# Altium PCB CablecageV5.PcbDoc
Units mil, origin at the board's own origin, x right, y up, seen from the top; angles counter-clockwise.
Board outline 745.03 x 1580.03 mil, 2 copper layers (Top Layer, Bottom Layer); 12 components, 19 nets, 69 pads, 70 vias.
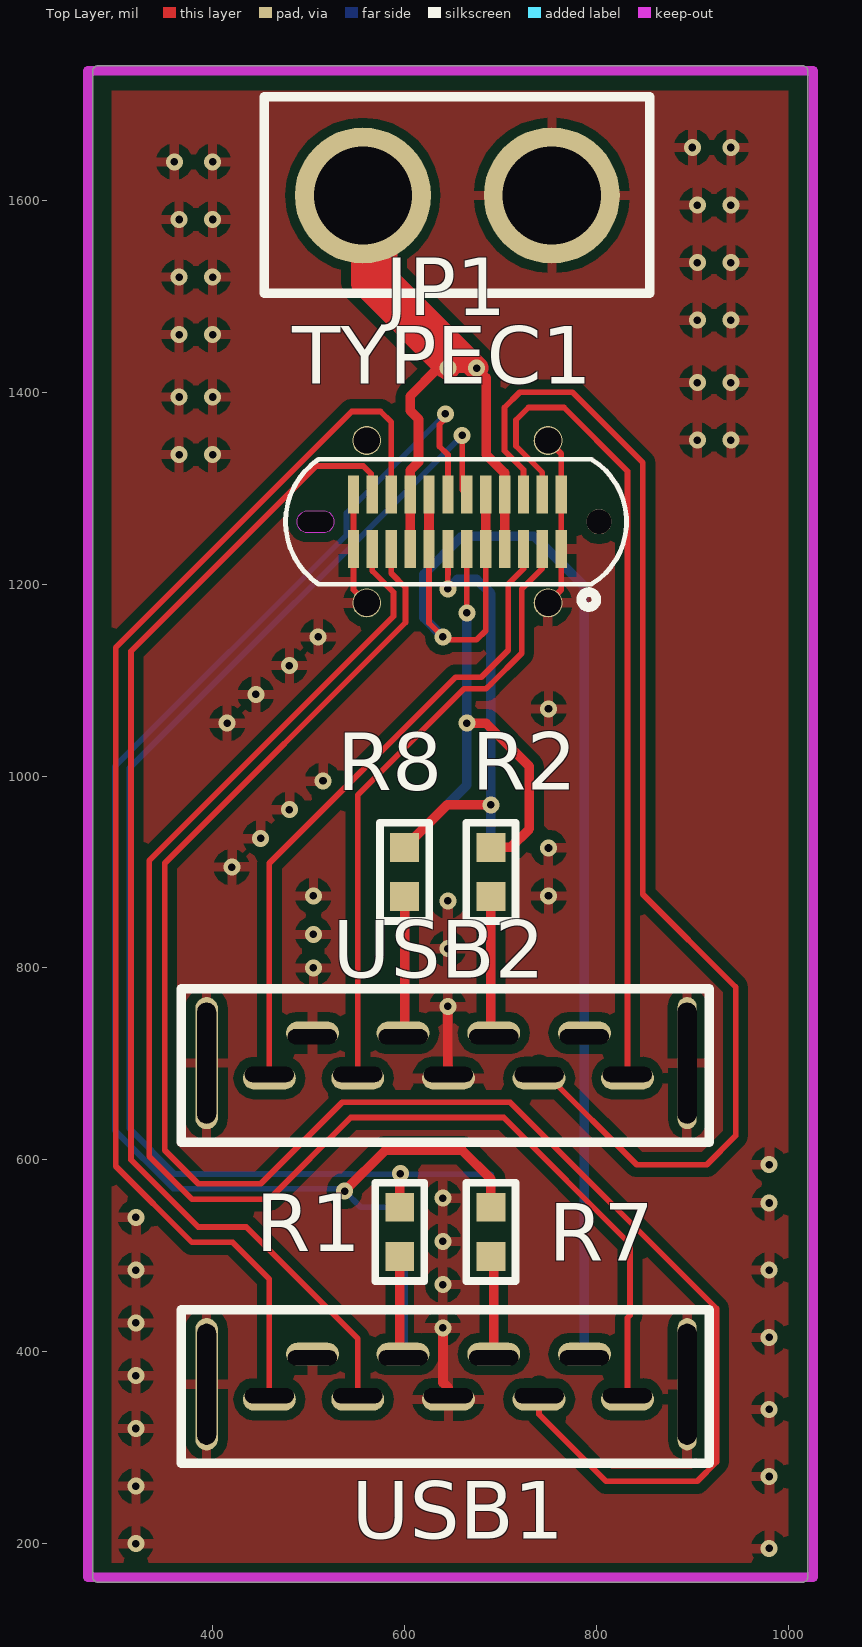
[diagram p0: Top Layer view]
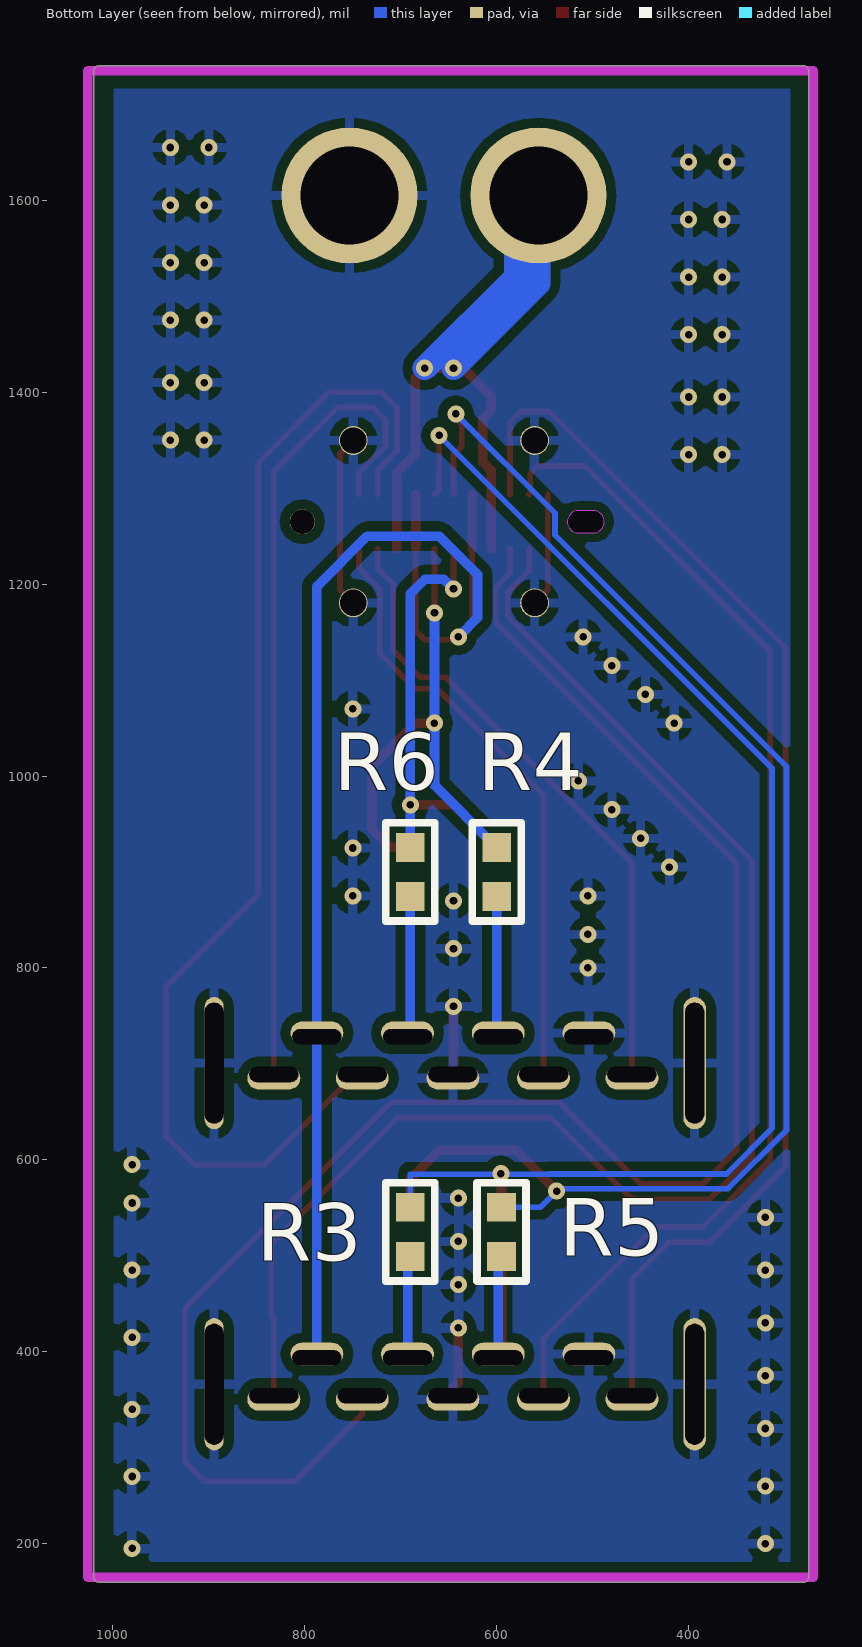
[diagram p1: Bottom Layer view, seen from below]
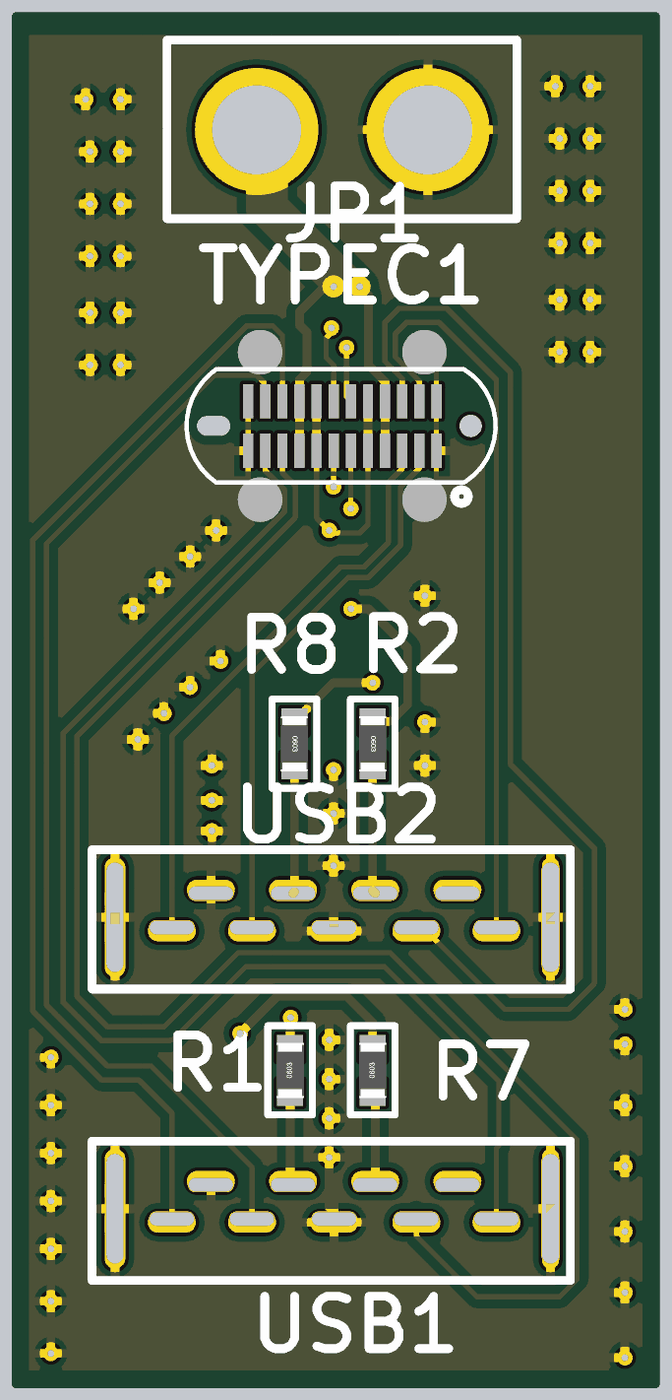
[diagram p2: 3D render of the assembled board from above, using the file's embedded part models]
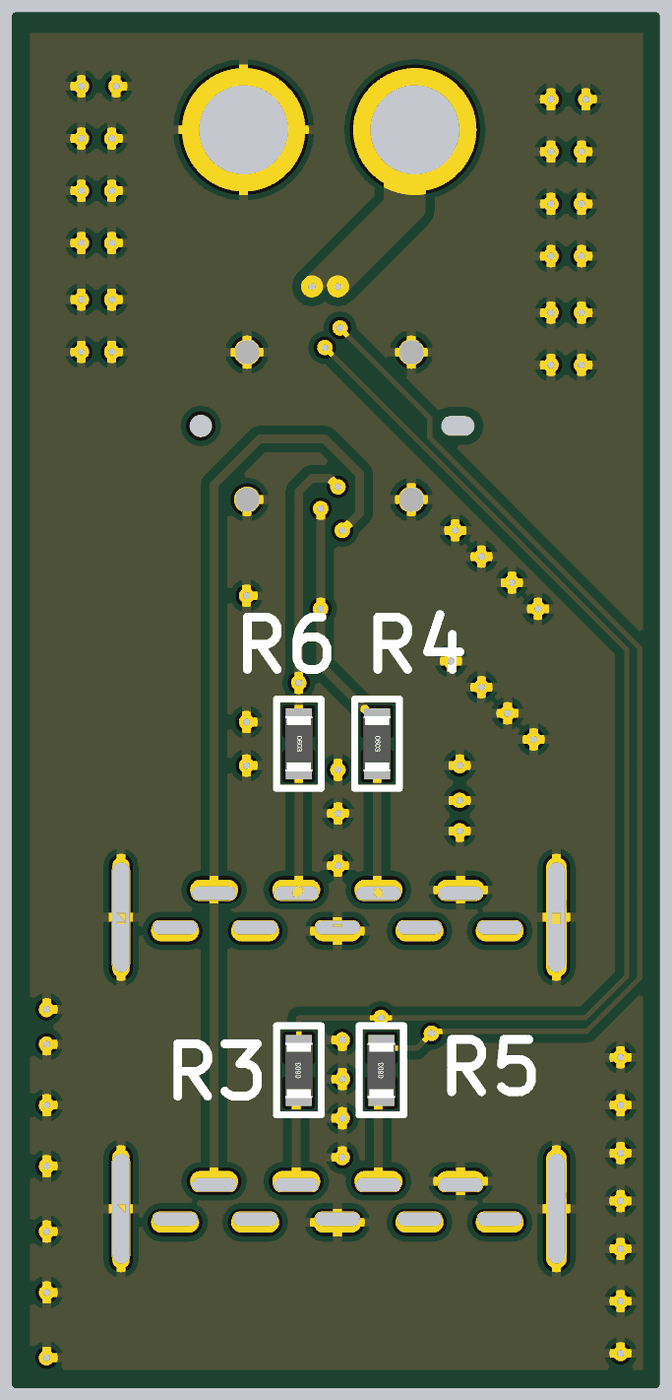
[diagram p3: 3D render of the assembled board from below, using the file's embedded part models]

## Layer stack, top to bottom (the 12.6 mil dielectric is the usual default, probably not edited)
Top Solder: solder mask 0.4, Solder Resist, Dk 3.5
Top Layer: signal copper 1.4
Dielectric 1: dielectric 12.6, FR-4, Dk 4.8
Bottom Layer: signal copper 1.4
Bottom Solder: solder mask 0.4, Solder Resist, Dk 3.5

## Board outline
274.99,165 274.99,1735 cw(c280,1735) 280,1740.02 1015,1740.02 cw(c1015,1735) 1020.01,1735 1020.01,165 cw(c1015,165) 1015,159.99 280,159.99 cw(c280,165)

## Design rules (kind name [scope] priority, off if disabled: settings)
Clearance [All] p1: gap=10 ignorepadtopadclearanceinfootprint=TRUE except(0: Arc-Hole Track-Hole SMDPad-Hole THPad-Hole Via-Hole Fill-Hole Poly-Hole Region-Hole Text-Hole; 6: Arc-Arc Arc-Track Arc-SMDPad Arc-THPad Arc-Via Track-Track Track-SMDPad Track-THPad Track-Via SMDPad-SMDPad SMDPad-THPad SMDPad-Via THPad-THPad THPad-Via Via-Via)
DiffPairsRouting [All] p1: maxlimit=50 minlimit=6 mostfreqgap=6 toplayer_minwidth=6 toplayer_maxwidth=15 toplayer_prefwidth=15 bottomlayer_minwidth=6 bottomlayer_maxwidth=15 bottomlayer_prefwidth=15 maxuncoupledlength=500
PolygonConnect [All] p1: connectstyle=Relief reliefconductorwidth=10 reliefentries=4 polygonreliefangle="90 Angle" airgapwidth=10
RoutingVias [All] p1: holewidth=28 width=50 viastyle="Through Hole" minholewidth=28 minwidth=50 maxholewidth=28 maxwidth=50
SolderMaskExpansion [All] p1: expansion=4
Width [All] p1: maxlimit=100 minlimit=6 preferedwidth=20 minimp=50.000000 maximp=50.000000 favimp=50.000000
29 further rules are at their usual default settings.

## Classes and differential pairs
component class draft_v2: JP1 R1 R2 R3 R4 R5 R6 R7 R8 TYPEC1 USB2
differential pair USB3-T: +USB3-T_P -USB3-T_N
differential pair USB3-T2: +USB3-T2_P -USB3-T2_N
differential pair USB3-R: +USB3-R_P -USB3-R_N
differential pair USB3-R2: +USB3-R2_P -USB3-R2_N
differential pair D4: +D4_P -D4_N
differential pair D3: +D3_P -D3_N

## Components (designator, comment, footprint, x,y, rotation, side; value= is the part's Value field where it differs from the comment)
JP1 "HDR-1X2" XT30 655,1605 r0 top
R1 "1K" "R 0603_L" 595,525 r90 top
R2 "1K" "R 0603_L" 690,900 r270 top
R3 "1K" "R 0603_L" 690,525 r90 bottom
R4 "1K" "R 0603_L" 600,900 r270 bottom
R5 "1K" "R 0603_L" 595,525 r90 bottom
R6 "1K" "R 0603_L" 690,900 r270 bottom
R7 "1K" "R 0603_L" 690,525 r90 top
R8 "1K" "R 0603_L" 600,900 r270 top
TYPEC1 "USB31-TYPEC-33141-2FS" USB-C-SMD_TYPEC-501S-ACP24H104 655,1265 r180 top
USB1 "FUS301-FDBU1K" USB3.0-MALE-0.8D 787.4,393.7 r180 top
USB2 "FUS301-FDBU1K" USB3.0-MALE-0.8D 787.4,728.35 r180 top

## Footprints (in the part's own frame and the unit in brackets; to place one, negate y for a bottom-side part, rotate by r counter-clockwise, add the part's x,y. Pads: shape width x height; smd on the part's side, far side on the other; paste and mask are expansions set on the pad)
"R 0603_L" [mil] "1/10W贴片电阻                 淘宝ID:黄晶宝石"
  rect 30x30 smd: 1(-25.59,0) 2(25.59,0)
  silkscreen extent -51,-26 51,26, body extent -31,-16 31,16, height 16
USB3.0-MALE-0.8D [mm]
  oval 1.4x0.6 hole 0.4 slot 1.3 at 0 deg copper offset 0,-0.1: 1(0,0) 2(2.4,0) 3(4.8,0) 4(7.2,0)
  oval 1.4x0.6 hole 0.4 slot 1.3 at 0 deg copper offset 0,0.1: 5(8.34,1) 6(6,1) 7(3.6,1) 8(1.2,1) 9(-1.14,1)
  oval 0.5x3.5 hole 3.2 slot 0.5 at 0 deg: 10(-2.72,0.7)
  oval 0.6x3.5 hole 3.2 slot 0.5 at 0 deg: 10(10,0.7)
  silkscreen extent -3.3,-1.27 10.67,2.79
USB-C-SMD_TYPEC-501S-ACP24H104 [mm]
  round 0.762 hole 0.7: 0(-2.4,2.15) 0(-2.4,-2.15) 0(2.4,2.15) 0(2.4,-2.15)
  rect 0.3x1 smd: A1(-2.75,0.72) A2(-2.25,0.72) A3(-1.75,0.72) A4(-1.25,0.72) A5(-0.75,0.72) A6(-0.25,0.72) A7(0.25,0.72) A8(0.75,0.72) A9(1.25,0.72) A10(1.75,0.72) A11(2.25,0.72) A12(2.75,0.72) B1(2.75,-0.72) B2(2.25,-0.72) B3(1.75,-0.72) B4(1.25,-0.72) B5(0.75,-0.72) B6(0.25,-0.72) B7(-0.25,-0.72) B8(-0.75,-0.72) B9(-1.25,-0.72) B10(-1.75,-0.72) B11(-2.25,-0.72) B12(-2.75,-0.72)
  round 0.66 hole 0.66 unplated: ""(-3.75,0)
  Keep-Out Layer board cut-out: 4.244,0 4.244,-0.056 4.203,-0.16 4.126,-0.241 4.024,-0.287 3.968,-0.29 3.968,-0.29 3.968,-0.29 3.556,-0.29 3.499,-0.289 3.393,-0.245 3.312,-0.163 3.268,-0.057 3.268,0 3.268,0 3.268,0 3.268,0.058 3.312,0.164 3.393,0.245 3.499,0.29 3.556,0.29 3.556,0.29 3.556,0.29 3.97,0.29 4.026,0.287 4.127,0.24 4.203,0.159 4.244,0.056 4.244,0 4.244,0 4.244,0 4.244,0
  Keep-Out Layer board cut-out: 3.97,-0.29 3.968,-0.29 3.968,-0.29 3.968,-0.29 3.968,-0.29 3.968,-0.29 3.968,-0.29 3.968,-0.29 3.968,-0.29
  silkscreen extent -4.48,-1.65 4.55,2.26
XT30 [mm]
  round 3.6 hole 2.6: 1(-2.5,0) 2(2.5,0)
  silkscreen extent -5.12,-2.59 5.09,2.62

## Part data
JP1: library part "Header 2", "2P接插件"
R1 R2 R3 R4 R5 R6 R7 R8: library part R, "贴片电阻"
TYPEC1: BOM_JLCPCB Part Class="Extended Part", BOM_Manufacturer="XKB Enterprise"
USB1 USB2: BOM_JLCPCB Part Class="Extended Part", BOM_Manufacturer=TXGA

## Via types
v1: diameter 17.72, hole 7.87, Top Layer to Bottom Layer, 70 vias

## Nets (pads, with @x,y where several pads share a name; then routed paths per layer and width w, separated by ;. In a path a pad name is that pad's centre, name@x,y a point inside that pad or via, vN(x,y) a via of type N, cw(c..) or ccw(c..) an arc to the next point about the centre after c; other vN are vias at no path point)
5.0V: TYPEC1.A5 TYPEC1.A8 TYPEC1.B5 TYPEC1.B8 USB1.1 USB2.1 | length 1428.8
  Top Layer w6: TYPEC1.A8 625.47,1159.53 v1(640,1145) 643,1142 675.03,1142 684.53,1151.5 TYPEC1.A5
  Top Layer w10: TYPEC1.A8 TYPEC1.B5 ; TYPEC1.A5 TYPEC1.B8
  Bottom Layer w10: v1(640,1145) 620,1165 620,1210 660,1250 735,1250 787.4,1197.6 USB2.1 USB1.1
D3_N: R4.2 R8.2 USB2.3 | length 293.4
  Top Layer w10: USB2.3 600,729.92 R8.2
  Bottom Layer w10: USB2.3 600,729.92 R4.2
D3_P: R2.2 R6.2 USB2.2 | length 294.5
  Top Layer w10: R2.2 690,731.26 USB2.2
  Bottom Layer w10: R6.2 690,731.26 USB2.2
D4_N: R1.1 R5.1 USB1.3 | length 214.2
  Top Layer w10: R1.1 595,397.12 USB1.3
  Bottom Layer w10: R5.1 598.43,495.98 USB1.3
D4_P: R3.1 R7.1 USB1.2 | length 213.8
  Top Layer w10: R7.1 692.91,496.5 USB1.2
  Bottom Layer w10: R3.1 692.91,496.49 USB1.2
GND: JP1.2 TYPEC1.0 TYPEC1.A1 TYPEC1.A12 TYPEC1.B1 TYPEC1.B12 USB1.4 USB1.7 USB1.10 USB2.4 USB2.7 USB2.10 | length 428
  Top Layer w6: TYPEC1.B1 TYPEC1.A12 546.73,1194.13 TYPEC1.0@560.51,1180.36 ; TYPEC1.0@749.49,1180.36 763.27,1194.13 TYPEC1.A1 TYPEC1.B12 763.27,1335.87 TYPEC1.0@749.49,1349.64
  Top Layer w10: v1(640,425) 640,367.87 645.67,362.2 ; v1(645,760) 645,697.52 645.67,696.85
  other v1: 980,195 320,200 320,260 980,270 320,320 980,340 320,375 980,415 320,430 640,470 320,485 980,485 640,515 320,540 980,555 640,560 980,595 505,800 645,820 505,835 645,870 505,875 750,875 420,905 750,925 450,935 480,965 515,995 415,1055 750,1070 445,1085 480,1115 510,1145 365,1335 400,1335 905,1350 940,1350 365,1395 400,1395 905,1410 940,1410 365,1460 400,1460 905,1475 940,1475 365,1520 400,1520 905,1535 940,1535 365,1580 400,1580 905,1595 940,1595 360,1640 400,1640 900,1655 940,1655
NetR1_2: R1.2 R3.2 TYPEC1.B7 | length 1396.1
  Top Layer w6: v1(660,1355) 660,1316.82 660.07,1316.76 660.07,1298.13 TYPEC1.B7
  Top Layer w10: R1.2 595,585 v1(595.63,585.63)
  Bottom Layer w6: v1(660,1355) 313,1008 313,632.83 360.47,585.36 544.9,585.36 545.26,585 690,585 R3.2
NetR2_1: R2.1 R4.1 TYPEC1.A6 | length 534.6
  Top Layer w6: v1(664.84,1170) TYPEC1.A6
  Top Layer w10: v1(665,1055) 685,1055 730,1010 730,945 710.59,925.59 R2.1
  Bottom Layer w10: R4.1 664.84,990.43 v1(664.84,1170)
NetR5_2: R5.2 R7.2 TYPEC1.B6 | length 1527.4
  Top Layer w6: v1@640,1380 v1(642.58,1377.42) 645.16,1374.84 636.51,1366.19 636.51,1343.49 645.16,1334.84 TYPEC1.B6
  Top Layer w10: v1(537.5,567.5) 580,610 660,610 690,580 R7.2
  Bottom Layer w6: R5.2 554.41,550.59 v1(537.5,567.5) 535,570 358.86,570 298,630.86 298,1009.97 539.34,1251.31 539.34,1274.17 v1(642.58,1377.42)
NetR6_1: R6.1 R8.1 TYPEC1.A7 | length 469.9
  Top Layer w6: v1(645,1195) 645,1210 645.16,1210.16 TYPEC1.A7
  Top Layer w10: R8.1 644.4,970 v1(690,970)
  Bottom Layer w10: v1(645,1195) 655,1205 675,1205 690,1190 R6.1
USB3-R2_N: TYPEC1.A10 USB1.8 | length 1852.1
  Top Layer w6: TYPEC1.A10 586.1,1211.33 601,1196.43 601,1160 350,909 350,610 385,575 450,575 535,660 710,660 925,445 925,285 905,265 810,265 740.16,334.84 USB1.8
USB3-R2_P: TYPEC1.A11 USB1.9 | length 1508.3
  Top Layer w6: TYPEC1.A11 566.42,1213.58 588.51,1191.49 588.51,1166.51 334,912 334,603.37 378.37,559 456.63,559 457.63,560 460,560 544,644 703.37,644 835,512.37 835,438.13 832.28,435.42 832.28,362.2
USB3-R_N: TYPEC1.B10 USB2.8 | length 1278.1
  Top Layer w6: TYPEC1.B10 723.9,1319.13 704,1339.03 704,1384 720,1400 775,1400 848.28,1326.72 848.28,876.72 945,780 945,625 915,595 842.01,595 748.03,688.98 USB2.8
USB3-R_P: TYPEC1.B11 USB2.9 | length 859.1
  Top Layer w6: TYPEC1.B11 743.58,1316.42 716,1344 716,1371 729,1384 766,1384 832.28,1317.72 832.28,696.85
USB3-T2_N: TYPEC1.B3 USB1.5 | length 1332.2
  Top Layer w6: 459.06,362.2 459.06,475.94 421,514 378.37,514 299,593.37 299,1134 545,1380 575,1380 586.1,1368.9 TYPEC1.B3
USB3-T2_P: TYPEC1.B2 USB1.6 | length 1250.4
  Top Layer w6: 551.18,362.2 551.18,413.82 435,530 385,530 315,600 315,1130 508,1323 557,1323 565,1315 565,1294.77 TYPEC1.B2
USB3-T_N: TYPEC1.A3 USB2.5 | length 665.3
  Top Layer w6: 459.06,696.85 459.06,909.06 653,1103 679.97,1103 708,1131.03 708,1200 723.9,1215.9 TYPEC1.A3
USB3-T_P: TYPEC1.A2 USB2.6 | length 633
  Top Layer w6: 551.18,696.85 551.18,980.18 662,1091 684.94,1091 689.94,1096 690,1096 722,1128 722,1195 743.58,1216.58 TYPEC1.A2
VCC: JP1.1 TYPEC1.A4 TYPEC1.A9 TYPEC1.B4 TYPEC1.B9 | length 1339.5
  Top Layer w10: TYPEC1.A9 TYPEC1.B4 605.79,1318.56 614.51,1327.28 614.51,1372.01 605.79,1380.73 605.79,1395.79 635,1425 v1(645,1425) v1(675,1425) 685,1415 685,1335 704.21,1315.79 TYPEC1.B9 TYPEC1.A4
  Top Layer w25: v1(645,1425) 556.57,1513.43 JP1.1 580,1581.57 580,1520 v1(675,1425)
  Bottom Layer w25: v1(645,1425) 556.57,1513.43 JP1.1 580,1581.57 580,1520 v1(675,1425)
pads on no net: TYPEC1.

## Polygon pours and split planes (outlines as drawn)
GND on Bottom Layer "GND_L02_P002" (solid, remove dead copper, pour order 2): 294,1716 294,181 999,181 999,1716
GND on Top Layer "GND_L01_P000" (solid, remove dead copper, pour order 0): 295,1714 295,179 1000,179 1000,1714

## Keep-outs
Keep-Out Layer:
  lines w10: 270,165 1026,165 1026,1735 270,1735 270,165

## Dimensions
270,165 to 1026,165 on Mechanical 15
270,1735 to 270,165 on Mechanical 15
